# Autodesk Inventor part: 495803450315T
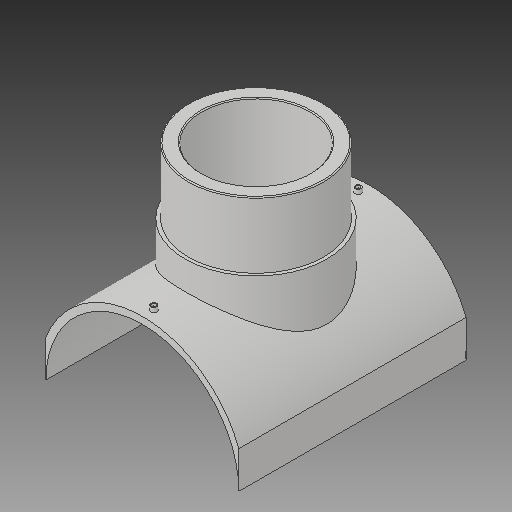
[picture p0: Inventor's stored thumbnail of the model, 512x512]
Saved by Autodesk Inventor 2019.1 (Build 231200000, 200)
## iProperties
Created: 2017-10
Part Number: 495803450315T
Material: Generic
Description: PLASSON BRANCH SADDLE  450x315
Document SubType Name: Modeling
Designer: KIM
Mass: 2754.05 g
Surface Area: 3037.44 cm^2
Volume: 2754.05 cm^3
Density: 1 g/cm^3
Appearance: Default
Author: KIM
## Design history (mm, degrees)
derived "495803.ipt"
feature "Solid1::495803.ipt"
tag "TaggingFeature1"
body "Solid1"
other parameters: "d1" = 16, "d4" = 0, "d12" = 250.6, "d13" = 14, "d14" = 238.5, "d16" = 5 deg, "d18" = 4, "d19" = 14, "d20" = 0, "d21" = 3, "d22" = 0, "d23" = 461, "d24" = 330.75, "d25" = 16, "d26" = 252, "d28" = 0, "d29" = 9.6, "d31" = 0, "d33" = 0, "d34" = 4.5, "d36" = 315, "d37" = 154, "d38" = 0, "d39" = 2.25, "d_1" = 315, "x_" = 16, "D_" = 16
